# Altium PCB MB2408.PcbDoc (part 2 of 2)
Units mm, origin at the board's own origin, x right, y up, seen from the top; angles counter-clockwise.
Board outline 43 x 47 mm, 2 copper layers (Top Layer, Bottom Layer), stack 0.996 mm thick; 66 components, 54 nets, 306 pads, 690 vias.
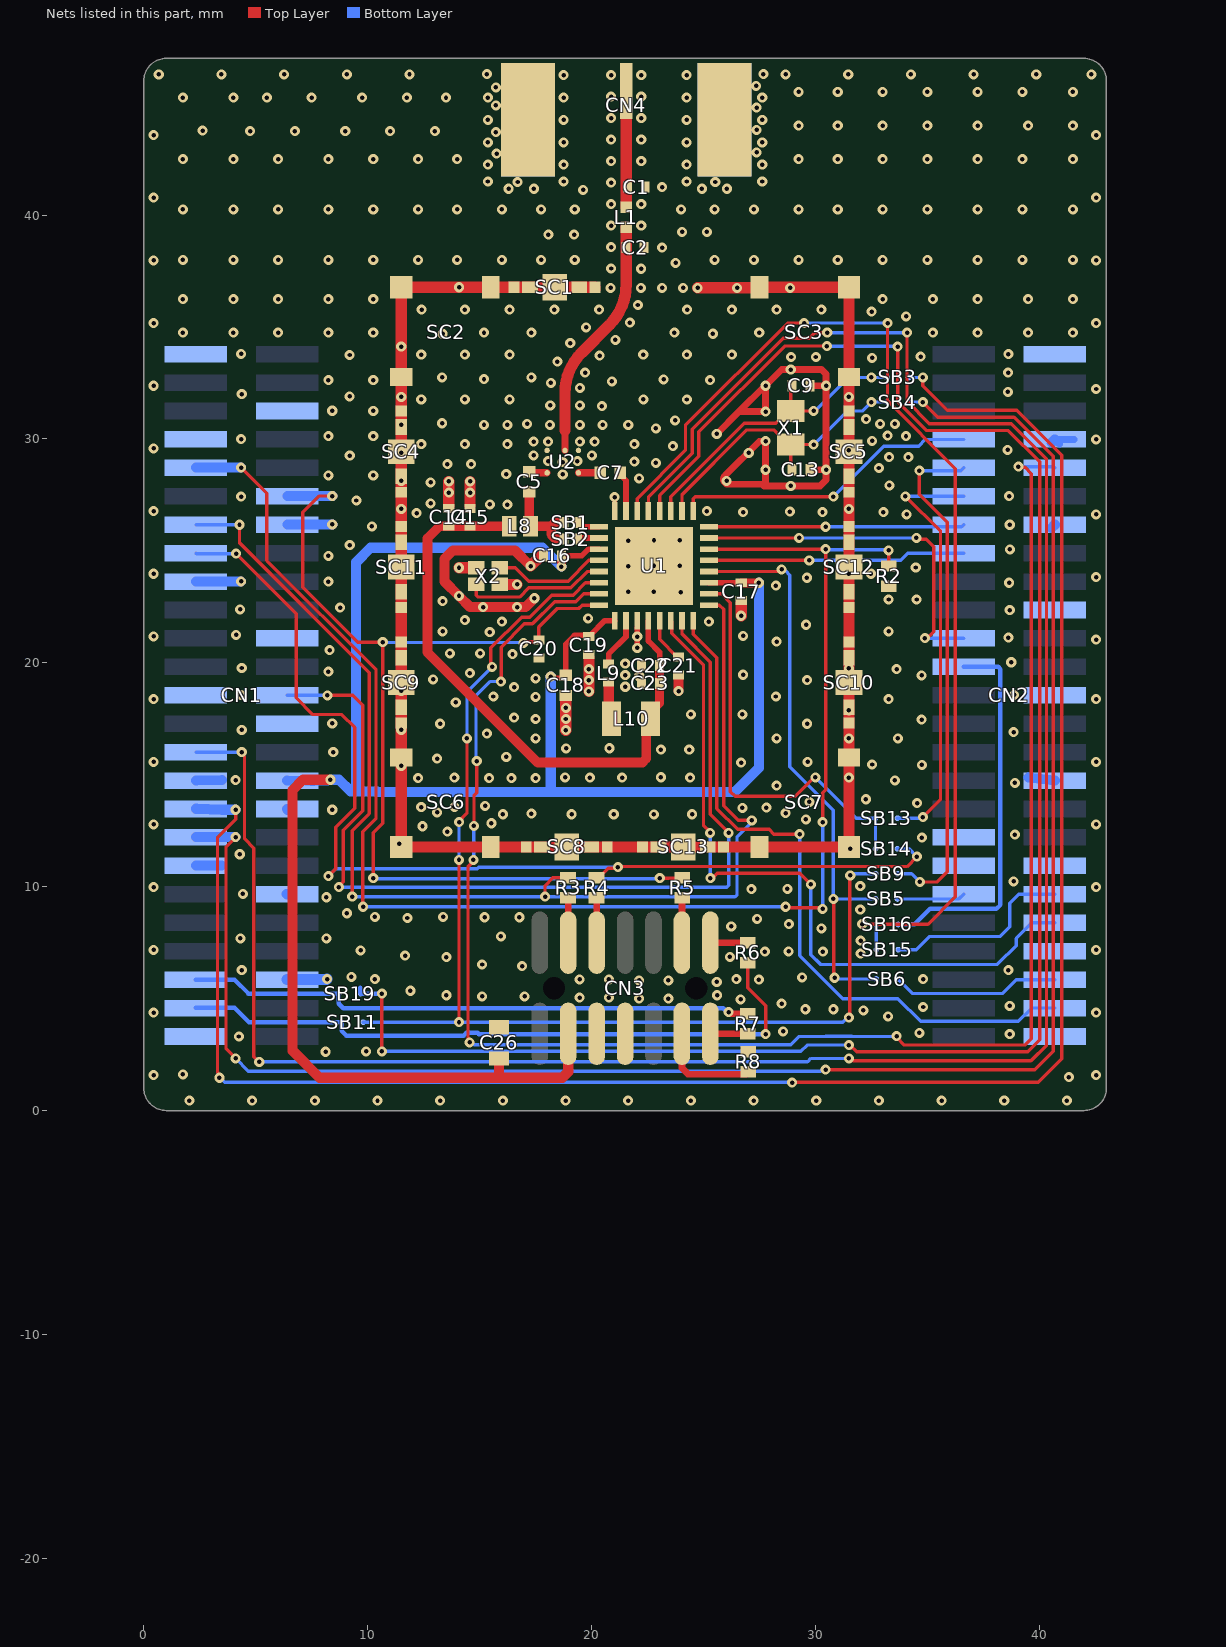
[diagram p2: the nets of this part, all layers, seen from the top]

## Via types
v1: diameter 0.45, hole 0.2, Top Layer to Bottom Layer, tented both sides, 690 vias

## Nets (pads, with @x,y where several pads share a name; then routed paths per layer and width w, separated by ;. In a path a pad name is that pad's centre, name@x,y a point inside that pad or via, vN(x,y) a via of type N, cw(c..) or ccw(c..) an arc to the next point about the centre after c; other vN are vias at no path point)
GND: C1.1 C2.1 C9.1 C13.1 C14.1 C15.1 C16.1 C17.1 C18.1 C19.2 C20.1 C21.1 C22.1 C23.1 C26.1 CN1.1 CN1.6 CN1.7 CN1.14 CN1.17 CN1.22 CN1.25 CN1.28 CN1.31 CN1.34 CN1.37 CN1.40 CN1.46 CN1.49 CN2.2 CN2.8 CN2.14 CN2.20 CN2.26 CN2.32 CN2.38 CN2.44 CN2.50 CN3.5 CN3.7 CN4.2 CN4.3 CN4.4 CN4.5 R2.1 R8.1 SC1.1 SC2.1 SC3.1 SC4.1 SC5.1 SC6.1 SC7.1 SC8.1 SC9.1 SC10.1 SC11.1 SC12.1 SC13.1 U1.16 U1.27 U1.33 U2.B1 U2.B3 X2.2 X2.4 | length 141
  Top Layer w0.2: v1(21.035,27.402) 21.038,27.399 21.038,26.78 U1.16@21.042,26.777
  Top Layer w0.25: v1(22.042,20.669) v1(22.042,21.17) U1.27@22.042,21.564
  Top Layer w0.3: v1@16.675,23.5 v1(16.68,23.505) ; SC1.1@20.16,36.775 20.16,36.765 SC1.1@20.25,36.675 ; v1(25.594,30.226) 26.593,31.225 ; C13.1@29.8,28.625 v1(30.475,28.625) ; C9.1@29.8,32.375 v1(30.475,32.375) ; 26.593,31.225 v1(27.775,31.225) v1(27.775,32.375) ; 26.593,31.225 27.743,32.375 v1(27.775,32.375) ; 27.775,27.975 27.7,27.9 v1(28.9,27.9) 30.214,27.9 30.475,28.161 v1(30.475,28.625) ; 27.775,27.975 v1(27.775,28.625) v1(27.775,29.9) 27.766,29.891 27.491,29.891 25.959,28.359 ccw(c26.118,28.2) 26.118,27.975 27.775,27.975 ; v1(27.775,32.375) 28.5,33.1 v1(28.9,33.1) 30.275,33.1 30.475,32.9 v1(30.475,32.375) ; v1(30.475,28.625) v1(30.475,32.375)
  Top Layer w0.45: v1(14.08,24.245) v1@14.085,24.25 ; v1(17.275,24.32) 16.57,25.025 13.809,25.025 13.425,24.642 13.425,23.642 v1(14.08,22.988) 14.58,22.488 v1(15.155,22.488) v1(16.68,22.488) 17.053,22.488 v1(17.449,22.883) ; v1@23.88,18.742 C21.1@23.88,19.339
  Top Layer w0.5: C14.1@13.625,27 v1(13.625,27.6) v1(13.625,28.1) ; v1@14.085,24.25 X2.4@14.855,24.25 ; C15.1@14.575,27 v1(14.575,27.6) v1(14.575,28.1) ; SC2.1@15.5,36.675 SC2.1@15.5,36.775 ; X2.2@15.905,23.5 v1@16.675,23.5 ; SC1.1@16.54,36.775 16.25,36.775 ; v1(17.275,24.32) 17.731,24.776 C16.1@17.759,24.776 ; v1(18.852,16.99) v1(18.852,17.49) v1(18.852,17.99) C18.1@18.852,18.39 ; v1(19.882,18.723) v1(19.882,19.223) v1(19.882,19.723) C19.2@19.882,20.223 ; SC1.1@20.16,36.775 SC1.1@19.45,36.775 SC1.1@18.35,36.775 SC1.1@17.25,36.775 SC1.1@16.54,36.775 16.267,36.775 ccw(c16.268,36.45) 16.25,36.775 ; v1(24.743,36.75) v1(26.5,36.75) SC3.1@27.475,36.75 ; v1(26.685,22.1) C17.1@26.685,22.675 ; SC3.1@27.5,36.775 SC3.1@31.5,36.775 SC3.1@31.5,32.775 SC5.1@31.5,31.243 SC5.1@31.5,30.533 SC5.1@31.5,29.433 SC5.1@31.5,28.333 SC5.1@31.5,27.623 31.5,26.875 SC12.1@31.5,26.088 SC12.1@31.5,25.378 31.5,25.078 31.5,24.578 SC12.1@31.5,24.278 v1(31.5,23.977) SC12.1@31.5,23.178 SC12.1@31.5,22.468 31.5,22.465 v1(31.5,19.75) v1(31.5,17.875) v1(31.5,16.625) SC7.1@31.5,15.775 v1(31.5,14.875) SC7.1@31.5,11.775 SC7.1@27.5,11.775 23.31,11.775 19.69,11.775 SC6.1@15.5,11.775 SC6.1@11.5,11.775 v1(11.5,15.395) SC6.1@11.5,15.775 SC9.1@11.5,17.31 SC9.1@11.5,18.02 SC9.1@11.5,19.12 SC9.1@11.5,20.22 SC9.1@11.5,20.93 SC11.1@11.5,22.468 SC11.1@11.5,23.178 SC11.1@11.5,24.278 SC11.1@11.5,25.378 SC11.1@11.5,26.088 SC4.1@11.5,27.623 SC4.1@11.5,28.333 v1(11.5,29.375) SC4.1@11.5,29.433 SC4.1@11.5,30.533 SC4.1@11.5,31.243 SC2.1@11.5,32.775 v1(11.5,34.125) SC2.1@11.5,36.775 SC2.1@15.5,36.775 ; SC2.1@15.5,36.775 16.25,36.775
  Bottom Layer w0.3: CN2.8@40.911,29.758 CN2.8@40.691,29.978 CN2.8@41.57,29.978
  Bottom Layer w0.45: CN1.37@2.343,10.94 CN1.37@3.462,10.943 ; CN1.31@2.343,14.75 CN1.31@3.501,14.762 ; CN1.17@2.343,23.64 v1(4.35,23.64) ; CN1.37@3.463,10.943 cw(c3.463,10.643) CN1.37@3.465,10.943 ; CN1.40@6.381,9.678 CN1.40@6.401,9.658 ; CN1.34@6.401,13.468 CN1.34@6.432,13.437 ; CN1.14@6.413,26.18 v1(8.42,26.18) ; CN2.32@39.521,14.883 CN2.32@40.691,14.738 ; CN2.14@40.546,26.023 CN2.14@40.691,26.168 ; CN2.8@40.546,29.833 CN2.8@40.691,29.978
  Bottom Layer w0.5: CN1.46@6.401,5.848 8.16,5.848 v1(8.187,5.875)
  other v1: 2.04,0.447 4.84,0.447 7.64,0.447 10.44,0.447 13.24,0.447 16.04,0.447 18.839,0.447 21.639,0.447 24.439,0.447 27.239,0.447 30.039,0.447 32.839,0.447 35.638,0.447 38.438,0.447 41.238,0.447 41.325,1.497 0.438,1.579 42.538,1.579 1.75,1.615 8.119,2.625 9.927,2.638 4.247,3.308 38.684,3.417 34.647,3.465 28.559,3.537 33.25,4.201 0.438,4.378 42.538,4.378 32.141,4.475 29.55,4.525 30.807,4.525 34.813,4.624 38.684,4.678 28.495,4.778 26.662,4.962 22.125,5 23.437,5 19.467,5.045 20.779,5.045 15.114,5.098 17.016,5.098 13.519,5.151 25.609,5.151 11.908,5.352 25.594,5.748 22.125,5.813 23.437,5.813 19.467,5.857 20.779,5.857 27.475,5.848 10.325,5.875 26.475,5.875 34.813,5.875 9.273,5.968 29.407,5.951 4.375,6.275 38.626,6.275 16.9,6.45 15.114,6.523 13.519,6.855 26.179,6.864 11.675,6.923 32.018,7.012 27.743,7.095 28.808,7.109 30.335,7.098 9.687,7.155 0.438,7.178 42.538,7.178 32.018,7.592 4.313,7.687 8.16,7.687 15.95,7.775 30.271,8.137 26.242,8.223 28.813,8.329 27.401,8.558 11.775,8.6 15.225,8.633 16.78,8.633 10.325,8.647 13.375,8.647 9.069,8.814 32.005,8.979 8.16,9.527 4.426,9.678 27.137,9.887 28.748,9.905 0.438,9.978 42.538,9.978 32.005,10.028 38.852,10.232 4.287,11.448 31.556,11.688 11.416,11.908 34.754,12.188 38.913,12.325 13.563,12.461 12.45,12.699 0.438,12.778 42.538,12.778 15.53,12.832 29.575,13.007 22.783,13.225 16.04,13.236 19.111,13.236 20.993,13.236 24.494,13.236 17.315,13.259 28.673,13.285 13.1,13.317 8.42,13.437 26.742,13.516 27.808,13.527 12.395,13.556 13.875,13.562 15.25,13.604 34.541,13.735 29.729,13.783 32.254,13.904 28.27,14.51 38.913,14.639 33.55,14.75 4.101,14.762 12.25,14.852 15.43,14.852 16.422,14.852 17.505,14.852 13.875,14.875 18.819,14.883 19.932,14.875 21.364,14.875 24.4,14.875 23.1,14.887 34.754,15.443 32.538,15.457 26.685,15.538 0.438,15.578 29.65,15.578 42.538,15.578 13.1,15.716 16.19,15.796 8.463,16.008 23.1,16.125 24.367,16.125 18.866,16.175 20.801,16.182 17.505,16.625 28.27,16.625 33.683,16.625 15.325,16.837 38.852,16.908 4.375,17 11.5,17 8.42,17.29 13.24,17.278 29.634,17.278 34.744,17.461 17.505,17.49 16.539,17.548 24.439,17.695 26.742,17.695 13.935,18.23 0.438,18.378 33.275,18.378 42.538,18.378 17.505,18.473 15.613,18.495 28.237,18.495 4.35,18.56 38.877,18.57 23.886,18.735 11.5,18.75 16.54,18.911 21.508,18.93 29.634,19.223 12.925,19.258 17.505,19.305 22.133,19.4 21.508,19.452 34.741,19.439 26.776,19.465 14.563,19.539 8.244,19.606 33.624,19.715 4.375,19.767 21.508,19.962 38.748,20.025 16.47,20.386 13.677,20.419 15.02,20.419 8.301,20.569 28.27,20.944 42.538,21.032 38.625,21.125 0.438,21.177 26.776,21.205 4.125,21.25 15.454,21.375 13.35,21.4 33.275,21.4 29.589,21.7 16,21.838 25.243,21.838 14.346,21.904 19.852,21.988 38.684,22.358 4.3,22.389 8.773,22.468 13.35,22.759 33.275,22.828 34.519,22.828 23.981,23.152 21.64,23.175 22.783,23.175 28.237,23.452 38.656,23.575 8.25,23.625 29.625,23.8 42.538,23.832 0.438,23.977 32.475,23.977 34.482,24.257 21.64,24.318 22.792,24.327 23.935,24.327 8.244,24.776 38.687,25.063 9.2,25.259 21.637,25.459 22.792,25.47 23.935,25.47 10.189,26.098 38.684,26.168 34.076,26.631 42.538,26.631 12.187,26.688 26.776,26.73 30.318,26.73 33.033,26.73 28.86,26.75 0.438,26.777 25.15,26.777 11.5,26.875 31.5,26.875 15.463,27.073 16.243,27.063 12.812,27.125 9.5,27.25 4.35,27.426 38.656,27.45 33.306,27.925 12.812,28.062 11.5,28.125 26.037,28.125 22.125,28.239 8.25,28.375 10.25,28.375 18.715,28.414 16.19,28.429 32.838,28.701 13.563,28.875 14.625,28.875 22.875,28.932 18.715,28.963 21.917,28.986 18.064,29.013 19.365,29.013 33.297,29.188 34.157,29.189 9.2,29.251 17.414,29.263 20.015,29.263 27.025,29.375 31.5,29.5 38.583,29.513 0.438,29.577 23.633,29.675 12.395,29.769 14.341,29.768 16.243,29.769 21.917,29.769 17.412,29.881 18.062,29.881 19.485,29.881 20.135,29.881 32.538,29.913 4.35,29.99 42.538,29.978 8.25,30.125 10.25,30.125 33.222,30.146 34.048,30.125 22.875,30.475 11.5,30.625 15.197,30.625 16.243,30.625 18.137,30.625 19.484,30.624 20.492,30.624 21.642,30.625 17.125,30.675 32.892,30.675 33.55,30.675 13.323,30.7 23.734,30.825 32.263,30.883 8.42,31.26 10.25,31.25 20.46,31.462 18.156,31.5 19.484,31.5 12.395,31.763 14.341,31.768 16.341,31.768 22.314,31.763 24.26,31.761 11.5,31.875 31.5,31.875 9.196,31.9 4.375,32 38.597,32.105 42.538,32.231 19.485,32.279 0.438,32.377 18.186,32.5 20.909,32.572 8.25,32.625 10.25,32.625 25.296,32.625 23.224,32.658 15.197,32.673 13.323,32.747 17.315,32.747 19.714,32.959 38.613,32.959 18.477,33.457 32.538,33.625 28.918,33.66 30.026,33.66 34.702,33.675 20.36,33.722 9.196,33.75 12.395,33.769 14.341,33.768 16.341,33.768 22.312,33.771 24.258,33.769 26.273,33.768 4.35,33.8 38.625,33.788 19.049,34.277 21.067,34.429 13.35,34.7 25.425,34.7 1.75,34.75 4,34.75 6,34.75 8.25,34.75 10.25,34.75 15.197,34.75 17.315,34.75 23.7,34.75 27.491,34.75 35.25,34.75 37.25,34.75 39.5,34.75 41.5,34.75 19.756,34.984 0.438,35.177 42.538,35.177 21.713,35.193 34.056,35.475 32.513,35.691 12.408,35.776 14.339,35.776 16.339,35.776 18.339,35.776 20.339,35.776 24.271,35.776 26.271,35.776 28.271,35.776 30.271,35.776 22.074,35.984 1.75,36.25 4,36.25 6,36.25 8.25,36.25 10.25,36.25 33,36.25 35.25,36.25 37.25,36.25 39.5,36.25 41.5,36.25 20.857,36.75 22.21,36.75 23.155,36.75 24.096,36.75 28.875,36.75 14.085,36.775 20.879,37.613 22.215,37.602 23.757,37.866 0.438,37.976 42.538,37.976 1.75,38 4,38 6,38 8.25,38 10.25,38 12.25,38 14,38 16,38 17.75,38 19.25,38 25.5,38 27.25,38 29.25,38 31,38 33,38 35,38 37.25,38 39.25,38 41.5,38 23.155,38.55 20.879,38.573 18.073,39.125 19.224,39.125 24.05,39.25 25.15,39.25 20.879,39.533 22.221,39.533 1.75,40.25 4,40.25 6,40.25 8.25,40.25 10.25,40.25 12.25,40.25 14,40.25 16,40.25 17.75,40.25 19.25,40.25 24,40.25 25.5,40.25 27.25,40.25 29.25,40.25 31,40.25 33,40.25 35,40.25 37.25,40.25 39.25,40.25 41.5,40.25 20.879,40.492 22.221,40.492 0.438,40.776 42.538,40.776 19.625,41.125 16.301,41.177 17.426,41.177 24.926,41.177 26.051,41.177 23.155,41.25 20.879,41.452 16.701,41.477 25.526,41.477 15.375,41.5 18.75,41.5 24.25,41.5 27.625,41.5 15.375,42.25 18.75,42.25 24.25,42.25 27.625,42.25 20.879,42.411 22.221,42.411 1.75,42.5 4,42.5 6,42.5 8.25,42.5 10.25,42.5 12.25,42.5 14,42.5 29.25,42.5 31,42.5 33,42.5 35,42.5 37.25,42.5 39.25,42.5 41.5,42.5 15.761,42.75 27.376,42.802 15.375,43.25 18.75,43.25 24.25,43.25 27.625,43.25 20.879,43.371 22.221,43.371 0.438,43.576 42.538,43.576 15.726,43.702 4.75,43.75 6.75,43.75 9,43.75 11,43.75 13,43.75 2.632,43.775 27.376,43.802 29.25,44 31,44 33,44 35,44 37.25,44 39.507,44 41.5,44 15.375,44.25 18.75,44.25 24.25,44.25 27.625,44.25 20.879,44.331 22.221,44.331 27.376,44.802 15.726,44.902 1.75,45.25 4,45.25 5.5,45.25 7.5,45.25 9.75,45.25 11.75,45.25 13.5,45.25 15.375,45.25 18.75,45.25 24.25,45.25 27.625,45.25 20.879,45.29 22.221,45.29 29.25,45.5 31,45.5 33,45.5 35,45.5 37.25,45.5 39.25,45.5 41.5,45.5 15.726,45.702 27.354,45.775 18.75,46.25 20.879,46.25 22.221,46.25 24.25,46.25 0.67,46.288 3.47,46.288 6.27,46.288 9.069,46.288 11.869,46.288 15.325,46.3 27.675,46.3 28.668,46.288 31.468,46.288 34.268,46.288 37.068,46.288 39.868,46.288 42.328,46.288
GPIO3/BOOT0: CN1.9 R2.2 U1.6 | length 69.8
  Top Layer w0.15: v1(4.35,28.72) 5.49,27.58 5.49,24.569 10.375,19.684 10.375,13.061 9.775,12.461 9.775,9.127 v1(9.8,9.102) ; U1.6@25.242,25.077 v1(30.457,25.077) 30.457,14.323 30.325,14.192 v1(30.325,12.886) ; v1(28.673,9.102) 28.72,9.055 30.278,9.055 v1(30.325,9.008) ; R2.2@33.275,24.325 v1(33.275,25.019)
  Bottom Layer w0.15: v1(9.8,9.102) v1(28.673,9.102) ; v1(30.325,9.008) v1(30.325,12.886) ; v1@30.457,25.063 30.471,25.048 33.246,25.048 v1(33.275,25.019)
  Bottom Layer w0.45: CN1.9@2.343,28.72 v1(4.35,28.72)
GPIO5/SWDIO: CN1.13 R3.2 U1.1 | length 54.8
  Top Layer w0.15: v1(4.275,26.168) 4.275,25.36 10.075,19.56 10.075,13.267 9.313,12.505 v1(9.313,9.555) ; v1(17.925,9.555) 17.925,10.049 18.276,10.4 R3.2@18.95,10.4 ; U1.1@25.242,22.577 25.712,22.577 25.9,22.389 25.9,13.615 26.554,12.961 v1(27.158,12.961)
  Bottom Layer w0.15: CN1.13@2.331,26.168 v1(4.275,26.168) ; v1(9.313,9.555) 26.412,9.555 26.5,9.643 26.5,12.222 27.158,12.88 v1(27.158,12.961)
GPIO6/SWCLK: CN1.15 R4.2 SB14.1 | length 48.4
  Top Layer w0.15: v1(4.126,24.875) 6.805,22.196 6.805,18.431 7.546,17.69 8.846,17.69 9.425,17.111 9.425,13.509 8.575,12.659 8.575,10.8 v1(8.25,10.475) ; R4.2@20.225,10.4 20.32,10.4 20.738,10.818 21.118,10.818 21.2,10.9 34.094,10.9 v1(34.532,11.338)
  Bottom Layer w0.15: CN1.15@2.331,24.898 2.354,24.875 v1(4.126,24.875) ; v1(8.25,10.475) 8.575,10.8 14.891,10.8 14.966,10.875 v1(21.175,10.875) ; SB14.1@33.662,11.688 34.182,11.688 v1(34.532,11.338)
GPIO12: CN1.26 U1.31 | length 42.2
  Top Layer w0.15: v1(8.2,18.548) 9.33,18.548 9.775,18.103 9.775,13.392 8.908,12.524 8.908,10.216 8.712,10.021 v1(8.712,9.978) ; U1.31@24.042,21.877 24.042,21.292 25.3,20.033 25.3,13.225 v1(26.125,12.4)
  Bottom Layer w0.15: CN1.26@6.401,18.548 v1(8.2,18.548) ; v1(8.712,9.978) 26.037,9.978 26.125,10.066 v1(26.125,12.4)
GPIO14: CN1.29 U1.13 | length 104.2
  Top Layer w0.15: v1(4.375,16.008) 4.375,15.927 4.501,15.801 4.501,12.137 4.916,11.722 4.916,2.405 5.143,2.177 v1(5.158,2.177) ; U1.13@22.542,26.777 22.545,26.78 22.545,27.402 24.497,29.355 24.497,30.438 28.559,34.5 29.725,34.5 29.975,34.75 v1(30.531,34.75) ; v1(31.5,2.325) 31.581,2.325 31.684,2.222 39.632,2.222 40.325,2.915 40.325,29.1 38.75,30.675 35.093,30.675 34.094,31.674 v1(34.094,34.75)
  Bottom Layer w0.15: CN1.29@2.331,16.008 v1(4.375,16.008) ; v1(5.158,2.177) 5.164,2.171 29.65,2.171 29.804,2.325 v1(31.5,2.325) ; v1(30.531,34.75) v1(34.094,34.75)
GPIO15/OSC32_IN: CN1.33 SB3.2 | length 87.8
  Top Layer w0.15: v1(3.375,1.465) 3.318,1.522 3.318,1.68 3.295,1.703 3.295,12.201 4.101,13.007 v1(4.101,13.437) ; v1(28.96,1.245) 28.983,1.268 39.958,1.268 41,2.31 41,29.274 38.999,31.275 35.891,31.275 34.8,32.366 v1(34.8,32.747)
  Bottom Layer w0.15: v1(3.375,1.465) 3.416,1.465 3.613,1.268 28.938,1.268 v1(28.96,1.245) ; SB3.2@34.1,32.747 SB3.2@34.175,32.747 v1(34.8,32.747)
  Bottom Layer w0.45: CN1.33@2.343,13.48 3.501,13.437 v1(4.101,13.437)
GPIO16/OSC32_OUT: CN1.35 SB4.2 | length 83.2
  Top Layer w0.15: v1(4.101,2.325) 3.675,2.751 3.675,11.784 v1(4.101,12.21) ; v1(30.457,1.828) 39.798,1.828 40.625,2.655 40.625,29.224 38.874,30.975 35.472,30.975 v1(34.8,31.647)
  Bottom Layer w0.15: v1(4.101,2.325) 4.669,1.757 30.219,1.757 30.232,1.77 30.399,1.77 v1(30.457,1.828) ; SB4.2@34.1,31.647 SB4.2@34.175,31.647 v1(34.8,31.647)
  Bottom Layer w0.45: CN1.35@2.343,12.21 v1(4.101,12.21)
GPIO23/VCP1_RX: CN1.45 R7.1 SB19.2 | length 25.5
  Top Layer w0.3: v1(26.125,4.4) 26.166,4.4 26.241,4.325 R7.1@26.975,4.325
  Bottom Layer w0.2: CN1.45@2.331,5.848 4.052,5.848 4.675,5.225 SB19.2@8.712,5.225 8.712,4.77 8.908,4.575 25.883,4.575 26.058,4.4 v1(26.125,4.4)
GPIO24/VCP1_TX: CN1.47 R6.2 SB11.1 | length 29.8
  Top Layer w0.15: R6.2@26.975,6.6 26.975,5.478 27.775,4.678 v1(27.775,3.417)
  Bottom Layer w0.2: CN1.47@2.331,4.598 4.052,4.598 4.7,3.95 SB11.1@8.825,3.95 8.835,3.94 8.835,3.565 9.05,3.35 14.284,3.35 14.399,3.465 14.909,3.465 14.958,3.417 v1(27.775,3.417)
GPIO28: CN2.7 U1.9 | length 13.7
  Top Layer w0.15: U1.9@24.542,26.777 24.542,27.328 24.634,27.42 v1(30.8,27.42)
  Bottom Layer w0.15: v1(30.8,27.42) 33.055,29.675 34.614,29.675 34.917,29.978 CN2.7@36.621,29.978
GPIO29: CN2.9 SB9.1 | length 23
  Top Layer w0.15: v1(34.647,28.585) 34.647,27.525 35.891,26.281 35.891,10.66 35.441,10.21 v1(34.667,10.21)
  Bottom Layer w0.15: SB9.1@33.662,10.582 34.297,10.582 v1(34.667,10.21) v1(34.667,10.21) ; v1(34.647,28.585) 36.498,28.585 CN2.9@36.621,28.708
GPIO30: CN2.10 U1.23 | length 77.2
  Top Layer w0.15: v1(14.557,3.042) 14.5,3.099 14.5,3.262 14.483,3.279 14.483,10.887 14.725,11.13 v1(14.725,11.2) ; v1(14.75,12.711) 14.75,14.071 14.875,14.196 v1(14.875,15.613) ; v1(15.95,19.164) 15.96,19.174 15.96,20.699 16.999,21.738 17.363,21.738 18.351,22.725 19.303,22.725 19.654,23.077 U1.23@20.342,23.077 ; v1(33.624,3.328) 33.624,3.264 33.963,2.925 39.35,2.925 39.637,3.212 39.637,28.455 39.365,28.728 39.1,28.728 v1(39.064,28.763)
  Bottom Layer w0.15: v1(14.557,3.042) 14.614,2.984 14.712,2.984 14.758,2.938 28.903,2.938 29.273,3.308 30.438,3.308 30.455,3.325 31.621,3.325 31.638,3.308 33.604,3.308 v1(33.624,3.328) ; v1(14.725,11.2) 14.737,11.212 14.737,12.699 v1(14.75,12.711) ; v1(14.875,15.613) 14.837,15.651 14.837,18.538 15.463,19.164 v1(15.95,19.164) ; v1(39.064,28.763) 40.636,28.763 CN2.10@40.691,28.708
GPIO31: CN2.11 SB13.1 | length 19.1
  Top Layer w0.15: v1(34.025,27.438) 35.591,25.872 35.591,13.898 v1(34.8,13.107)
  Bottom Layer w0.15: SB13.1@33.662,13.061 34.754,13.061 v1(34.8,13.107) ; v1(34.025,27.438) CN2.11@36.621,27.438
GPIO33: CN2.13 U1.8 | length 11.4
  Top Layer w0.15: U1.8@25.242,26.077 v1(30.457,26.077)
  Bottom Layer w0.15: v1(30.457,26.077) 32.947,26.077 32.949,26.075 36.528,26.075 CN2.13@36.621,26.168
GPIO34: CN2.15 U1.5 | length 11.5
  Top Layer w0.15: U1.5@25.242,24.577 25.243,24.576 29.724,24.576 v1(29.725,24.575)
  Bottom Layer w0.15: v1(29.725,24.575) 33.808,24.575 34.131,24.898 CN2.15@36.621,24.898
GPIO37: CN2.21 U1.7 | length 16.3
  Top Layer w0.15: U1.7@25.242,25.577 v1(29.273,25.577) ; v1(34.512,25.577) 34.57,25.52 34.962,25.52 35.291,25.19 35.291,21.387 35.114,21.21 35.079,21.21 34.969,21.1 v1(34.887,21.1)
  Bottom Layer w0.15: v1(29.273,25.577) v1(34.512,25.577) ; v1(34.887,21.1) 36.609,21.1 CN2.21@36.621,21.088
GPIO39: CN2.23 SB16.1 | length 17.2
  Bottom Layer w0.2: SB16.1@33.7,8.313 34.444,8.313 34.444,8.329 35.122,9.008 38.09,9.008 38.266,9.184 38.266,19.715 38.163,19.818 CN2.23@36.621,19.818
GPIO47: CN2.35
GPIO49: CN2.37
GPIO50: CN2.39 SB5.1 | length 3
  Bottom Layer w0.15: SB5.1@33.662,9.452 36.415,9.452 CN2.39@36.621,9.658
GPIO51: CN2.40 SB15.1 | length 8.6
  Bottom Layer w0.15: SB15.1@33.7,7.187 34.512,7.187 35.1,7.775 38.259,7.775 38.684,8.2 38.684,9.263 39.08,9.658 CN2.40@40.691,9.658
GPIO53: CN2.42 U1.30 | length 32.2
  Top Layer w0.15: U1.30@23.542,21.877 23.592,21.827 23.592,21.318 24.388,20.522 25,19.909 25,12.74 25.296,12.444 v1(25.296,12.4) ; v1(25.306,10.378) 25.387,10.378 25.609,10.6 29.303,10.6 v1(29.801,10.102)
  Bottom Layer w0.15: v1(25.296,12.4) 25.301,12.395 25.301,10.383 v1(25.306,10.378) ; v1(29.801,10.102) 29.801,6.962 30.24,6.523 38.109,6.523 38.163,6.577 38.179,6.577 38.965,7.362 38.965,7.687 39.666,8.388 CN2.42@40.691,8.388
GPIO56: CN2.46 SB6.1 | length 7.5
  Bottom Layer w0.15: SB6.1@33.696,5.875 34.346,5.225 38.342,5.225 38.965,5.848 CN2.46@40.691,5.848
GPIO57: CN2.48 U1.32 | length 31.3
  Top Layer w0.15: U1.32@24.542,21.877 24.542,21.281 25.6,20.223 25.6,13.491 26.53,12.561 27.932,12.561 28.143,12.35 v1(29.299,12.35)
  Bottom Layer w0.15: v1(29.299,12.35) 29.299,6.923 31.222,5 33.683,5 34.7,3.983 39.071,3.983 39.666,4.578 CN2.48@40.691,4.578
NetC1_2: C1.2 CN4.1 L1.2 | length 5.2
  Top Layer w0.51: L1.2@21.55,40.35 21.55,41.25 CN4.1@21.55,45.55
NetC2_2: C2.2 L1.1 U2.B2 | length 10.9
  Top Layer w0.32: U2.B2@18.815,29.488 18.815,30.378
  Top Layer w0.51: 18.816,30.378 18.816,32.058 cw(c21.356,32.058) 19.56,33.854 20.806,35.1 ccw(c19.01,36.896) 21.55,36.896 C2.2@21.55,38.55 L1.1@21.55,39.45
NetC5_1: C5.1 U2.A1 | length 0.8
  Top Layer w0.32: C5.1@17.225,28.488 U2.A1@18.016,28.488
NetC5_2: C5.2 L8.2 SB1.2 SB2.2 | length 4.2
  Top Layer w0.43: L8.2@17.215,26.11 C5.2@17.215,27.673 ; L8.2@17.225,26.221 ccw(c17.396,26.221) L8.2@17.275,26.1 18.193,26.1 ; SB1.2@18.698,26.266 18.359,26.266 18.193,26.1 ; SB2.2@18.76,25.535 18.399,25.535 18.193,25.74 18.193,26.1
NetC7_1: C7.1 U1.15 | length 1.8
  Top Layer w0.25: C7.1@21.24,28.488 21.24,28.438 21.542,28.137 U1.15@21.542,26.777
NetC7_2: C7.2 U2.A3 | length 1
  Top Layer w0.32: U2.A3@19.415,28.488 C7.2@20.44,28.488
NetC9_2: C9.2 SB3.1 U1.11 X1.2 | length 13.8
  Top Layer w0.15: U1.11@23.542,26.777 23.542,27.426 26.815,30.7 28.237,30.7 28.35,30.813 28.35,30.825 28.775,31.25 X1.2@28.9,31.25 ; C9.2@28.9,32.375 X1.2@28.9,31.25 ; v1@30.075,31.25 X1.2@28.9,31.25
  Bottom Layer w0.15: v1(29.925,31.25) 30,31.25 31.497,32.747 v1(32.5,32.747) SB3.1@33.2,32.747
NetC13_2: C13.2 SB4.1 U1.10 X1.1 | length 13.3
  Top Layer w0.15: U1.10@24.042,26.777 24.042,27.502 26.939,30.4 28.149,30.4 28.35,30.199 28.35,30.175 28.775,29.75 X1.1@28.9,29.75 ; C13.2@28.9,28.625 X1.1@28.9,29.75 ; v1(29.925,29.75) X1.1@28.9,29.75
  Bottom Layer w0.15: v1(29.925,29.75) 31.422,31.247 32.1,31.247 v1(32.5,31.647) SB4.1@33.2,31.647
NetC21_2: C21.2 U1.29 | length 2
  Top Layer w0.15: U1.29@23.042,21.877 23.042,21.049 23.833,20.258 C21.2@23.883,20.258
NetCN3_4: CN3.4 R3.1 | length 2
  Top Layer w0.3: R3.1@18.95,9.5 18.96,9.49 CN3.4@18.96,7.5
NetCN3_6: CN3.6 R4.1 | length 2
  Top Layer w0.3: R4.1@20.225,9.5 20.23,9.495 CN3.6@20.23,7.5
NetCN3_11: CN3.11 R8.2 | length 4.7
  Top Layer w0.3: CN3.11@24.04,3.43 24.04,1.897 24.312,1.625 26.903,1.625 R8.2@27.003,1.725 ; R8.2@26.914,1.814 R8.2@26.928,1.828
NetCN3_12: CN3.12 R5.1 | length 2
  Top Layer w0.3: CN3.12@24.04,7.5 24.04,9.49 R5.1@24.05,9.5
NetCN3_13: CN3.13 R7.2 | length 1.7
  Top Layer w0.3: CN3.13@25.31,3.43 25.315,3.425 R7.2@26.975,3.425
NetCN3_14: CN3.14 R6.1 | length 1.7
  Top Layer w0.3: CN3.14@25.31,7.5 R6.1@26.975,7.5
NetL9_1: L9.1 L10.2 | length 1.1
  Top Layer w0.47: L10.2@20.765,17.935 L9.1@20.765,18.993
NetL9_2: L9.2 U1.26 | length 2.3
  Top Layer w0.25: L9.2@20.765,19.921 20.765,20.386 21.542,21.163 U1.26@21.542,21.877
NetSB1_1: SB1.1 U1.17 | length 1
  Top Layer w0.25: SB1.1@19.375,26.266 ccw(c19.832,26.723) 19.832,26.077 U1.17@20.342,26.077
NetSB2_1: SB2.1 U1.18 | length 1
  Top Layer w0.25: SB2.1@19.375,25.525 19.427,25.577 U1.18@20.342,25.577
NetSB5_2: SB5.2 SB6.2 U1.4 | length 26.4
  Top Layer w0.15: U1.4@25.242,24.077 28.315,24.077 28.414,24.176 v1(28.495,24.176) ; v1(30.8,9.452) 30.828,9.424 30.828,5.959 v1(30.856,5.931)
  Bottom Layer w0.15: v1(28.495,24.176) 28.577,24.176 28.648,24.105 28.668,24.105 28.86,23.913 28.86,15.352 30.8,13.412 v1(30.8,9.452) SB5.2@32.687,9.452 ; v1(30.856,5.931) 30.913,5.875 SB6.2@32.721,5.875
NetSB9_2: SB9.2 SB11.2 U1.22 | length 52.7
  Top Layer w0.15: v1(14.08,3.95) v1(14.08,11.2) ; v1(14.085,12.886) 14.085,12.933 14.437,13.285 v1(14.437,16.625) ; v1(15.56,19.818) 15.504,19.874 15.504,20.667 16.875,22.038 17.239,22.038 18.227,23.025 19.178,23.025 19.73,23.577 U1.22@20.342,23.577 ; v1(31.498,4.147) 31.527,4.176 31.527,10.471 v1(31.556,10.5)
  Bottom Layer w0.15: SB11.2@9.8,3.95 31.22,3.95 31.417,4.147 v1(31.498,4.147) ; v1(14.08,11.2) 14.083,11.202 14.083,12.884 v1(14.085,12.886) ; v1(14.437,16.625) 14.437,18.695 v1(15.56,19.818) ; v1(31.556,10.5) 31.638,10.5 31.72,10.582 SB9.2@32.687,10.582
NetSB13_2: SB13.2 SB14.2 U1.2 | length 18.6
  Top Layer w0.15: U1.2@25.242,23.077 25.808,23.077 26.2,22.685 26.2,14.246 26.411,14.035 29.102,14.035 29.95,14.883 v1(30,14.883)
  Bottom Layer w0.15: v1(30,14.883) 31.822,13.061 SB13.2@32.687,13.061 SB14.2@32.687,11.688
NetSB15_2: SB15.2 SB16.2 U1.14 | length 49
  Top Layer w0.15: U1.14@22.042,26.777 22.042,27.33 24.197,29.486 24.197,30.606 28.77,35.178 v1(29.5,35.178) ; v1(32.093,8.329) 35.034,8.329 36.25,9.545 36.25,28.669 33.222,31.697 v1(33.222,35.178)
  Bottom Layer w0.15: v1(29.5,35.178) v1(33.222,35.178) ; v1(32.093,8.329) 32.109,8.313 SB16.2@32.725,8.313 SB15.2@32.725,7.187
NetSB19_1: SB19.1 U1.12 | length 84.1
  Top Layer w0.15: v1(10.632,2.64) v1(10.632,5.226) ; U1.12@23.042,26.777 23.042,27.475 24.797,29.23 24.797,30.314 28.633,34.15 v1(30.518,34.15) ; v1(31.5,2.925) 31.544,2.925 31.844,2.625 39.496,2.625 40.025,3.154 40.025,26.088 40.015,26.098 40.015,28.986 38.626,30.375 34.969,30.375 33.675,31.669 v1(33.675,34.125)
  Bottom Layer w0.15: v1(10.632,2.64) 29.349,2.64 29.634,2.925 v1(31.5,2.925) ; v1(30.518,34.15) 30.531,34.137 33.663,34.137 v1(33.675,34.125)
  Bottom Layer w0.2: 9.677,5.487 9.677,5.271 SB19.1@9.687,5.26 ; SB19.1@9.687,5.225 v1(10.632,5.226)
NetU1_20: U1.20 X2.3 | length 5.1
  Top Layer w0.15: X2.3@15.905,24.25 16.597,24.25 17.197,23.65 18.955,23.65 19.882,24.577 U1.20@20.342,24.577
NetU1_21: U1.21 X2.1 | length 6.5
  Top Layer w0.15: X2.1@14.855,23.5 14.855,23.025 14.943,22.938 16.784,22.938 17.197,23.35 19.079,23.35 19.806,24.077 U1.21@20.342,24.077
NRST: C20.2 CN1.12 R5.2 U1.24 | length 46.8
  Top Layer w0.15: v1(8.42,27.45) 7.825,27.45 7.105,26.73 7.105,23.379 9.561,20.922 v1(10.675,20.922) 10.675,12.834 10.25,12.409 v1(10.25,10.378) ; v1(16.958,20.887) 17.016,20.945 17.576,20.945 C20.2@17.65,21.019 17.65,21.6 18.476,22.425 19.427,22.425 19.579,22.577 U1.24@20.342,22.577 ; v1(23.048,10.378) 24.028,10.378 R5.2@24.05,10.4
  Bottom Layer w0.15: v1(10.25,10.378) 10.281,10.347 23.017,10.347 v1(23.048,10.378) ; v1(10.675,20.922) 10.692,20.905 16.941,20.905 v1(16.958,20.887)
  Bottom Layer w0.45: CN1.12@6.413,27.45 v1(8.42,27.45)
VDD: C16.2 C17.2 C18.2 C19.1 C26.2 CN1.32 CN3.3 U1.3 U1.19 U1.25 | length 94.3
  Top Layer w0.2: v1(18.18,19.379) 18.192,19.285 cw(c18.316,19.161) 18.316,19.336 18.695,19.336 18.853,19.339 C18.2@18.875,19.339 ; C18.2@18.875,19.34 18.875,20.296
  Top Layer w0.25: C16.2@18.65,24.776 19.557,24.776 19.858,25.077 U1.19@20.342,25.077 ; C18.2@18.853,19.339 18.853,20.836 19.239,21.223 19.932,21.223 20.586,21.877 U1.25@21.042,21.877 ; U1.3@25.242,23.577 26.683,23.577 C17.2@26.685,23.575
  Top Layer w0.4: C16.2@18.65,24.776 18.65,24.303 v1(18.653,24.301) ; C17.2@26.685,23.575 v1(27.475,23.575)
  Top Layer w0.45: v1(8.338,14.778) 7.105,14.778 6.65,14.323 6.65,2.666 7.851,1.465 9.025,1.465 15.875,1.465 ; C26.2@15.875,2.325 15.875,1.465 ; CN3.3@18.96,3.43 18.96,1.733 18.692,1.465 15.875,1.465
  Bottom Layer w0.45: CN1.32@6.401,14.738 7.503,14.712 ccw(c7.509,15.012) CN1.32@7.63,14.738 ; CN1.32@7.63,14.75 8.179,14.75 ccw(c8.179,15.05) v1@8.244,14.757 ; v1(8.338,14.778) 8.718,14.778 9.239,14.257 10.434,14.257 10.463,14.229 26.401,14.229 27.475,15.304 v1(27.475,23.575) ; 9.487,14.461 9.487,24.496 10.132,25.14 17.814,25.14 v1(18.653,24.301) ; 18.18,14.257 v1(18.18,19.379)
VFBSD: C14.2 C15.2 C22.2 C23.2 L8.1 L10.1 U1.28 | length 27.3
  Top Layer w0.25: U1.28@22.542,21.877 22.542,20.973 23.048,20.467 C22.2@23.048,20.025
  Top Layer w0.4: L10.1@22.446,17.505 22.446,17.606 23.033,18.193 C23.2@23.033,19.077 23.033,19.127 C22.2@23.033,19.873
  Top Layer w0.43: L8.1@16.272,26.1 C15.2@14.575,26.1 C14.2@13.625,26.1 13.21,26.1 12.674,25.564 12.674,20.467 17.595,15.546 22.276,15.546 22.446,15.716 L10.1@22.446,17.505
pads on no net: CART-1.1 CN1.2 CN1.3 CN1.4 CN1.5 CN1.8 CN1.10 CN1.11 CN1.16 CN1.18 CN1.19 CN1.20 CN1.21 CN1.23 CN1.24 CN1.27 CN1.30 CN1.36 CN1.38 CN1.39 CN1.41 CN1.42 CN1.43 CN1.44 CN1.48 CN1.50 CN2.1 CN2.3 CN2.4 CN2.5 CN2.6 CN2.12 CN2.16 CN2.17 CN2.18 CN2.19 CN2.22 CN2.24 CN2.25 CN2.27 CN2.28 CN2.29 CN2.30 CN2.31 CN2.33 CN2.34 CN2.36 CN2.41 CN2.43 CN2.45 CN2.47 CN2.49 CN3.1 CN3.2 CN3.8 CN3.9 CN3.10 CN3.NPTH1 CN3.NPTH2

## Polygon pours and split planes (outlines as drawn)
GND on Bottom Layer "GAGND_L02_P003" (solid, remove dead copper, pour order 3): 0,47 43,47 43,0 0,0
GND on Top Layer "GND_L01_P001" (solid, remove dead copper, pour order 1): 0,47 43,47 43,0 0,0

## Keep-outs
Top Layer:
  region: 14.155,23.87 14.08,23.87 cw(c14.08,24.25) 13.7,24.25 cw(c14.075,24.25) 14.075,24.625 15.225,24.625 15.225,23.875
  region: 13.091,26.75 13.091,28.091 cw(c13.625,28.091) 13.625,28.625 cw(c13.625,28.1) 14.15,28.1 14.15,26.75 14,26.75
  region: 14.041,26.75 14.041,28.091 cw(c14.575,28.091) 14.575,28.625 cw(c14.575,28.1) 15.1,28.1 15.1,26.75 14.95,26.75
  region: 15.954,24.804 19.448,24.804 19.448,25.74 15.954,25.74
Keep-Out Layer:
  lines w0.1: 41.875,-0.025 1.086,-0.025 cw(c1.086,1.088) -0.026,1.085 -0.026,45.891 cw(c1.086,45.888) 1.086,47.001 41.919,47 ; 41.917,47.001 cw(c41.916,45.889) 43.029,45.891 ; 41.919,-0.025 ccw(c41.916,1.088) 43.029,1.087 43.029,46

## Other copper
Top Layer:
  region net GND: 24.85,22.225 24.85,21.325 25.6,20.575 25.63,20.605 25.63,22.228
  region net GND: 18.142,28.76 18.165,28.748 18.187,28.734 18.208,28.718 18.227,28.701 18.245,28.681 18.261,28.66 18.275,28.638 18.287,28.615 18.297,28.591 18.305,28.566 18.31,28.54 18.314,28.515 18.315,28.488 18.315,28.163 19.115,28.163 19.115,28.488 19.116,28.515 19.12,28.54 19.125,28.566 19.133,28.591 19.143,28.615 19.155,28.638 19.169,28.66 19.185,28.681 19.203,28.701 19.222,28.718 19.243,28.734 19.265,28.748 19.288,28.76 19.312,28.77 19.337,28.778 19.363,28.784 19.389,28.787 19.415,28.788 19.74,28.788 19.74,28.988 20.49,28.988 20.49,30.113 19.114,30.113 19.114,29.488 19.113,29.462 19.11,29.436 19.104,29.411 19.096,29.386 19.086,29.362 19.074,29.338 19.06,29.316 19.044,29.296 19.026,29.276 19.007,29.259 18.986,29.243 18.964,29.229 18.941,29.217 18.917,29.206 18.892,29.199 18.866,29.193 18.84,29.19 18.814,29.188 18.788,29.19 18.762,29.193 18.736,29.199 18.711,29.206 18.687,29.217 18.664,29.229 18.642,29.243 18.621,29.259 18.602,29.276 18.584,29.296 18.568,29.316 18.554,29.338 18.542,29.362 18.532,29.386 18.524,29.411 18.519,29.436 18.515,29.462 18.514,29.488 18.514,30.113 16.94,30.113 16.94,28.988 17.69,28.988 17.69,28.788 18.015,28.788 18.041,28.787 18.067,28.784 18.093,28.778 18.118,28.77
  region net GND: 22.434,20.215 21.29,20.215 21.29,18.615 22.433,18.615
  region net GND: 27.775,30.094 27.775,28.044 25.893,28.044 25.777,28.161
  region net GND: 27.775,32.541 27.775,31.085 26.269,31.085
  region net NetC2_2: 18.591,30.275 18.656,30.142 18.818,30.142 18.819,30.141 18.976,30.141 19.039,30.275
  pour cut-out: 16.63,26.371 15.094,26.371 15.094,26.759 16.63,26.759
  pour cut-out: 21.672,30.378 21.672,27.277 16.488,27.277 16.488,30.378 18.098,30.378 19.536,30.378
  pour cut-out: 26.296,22.329 27.189,22.329 27.189,21.569 26.296,21.569
  pour cut-out: 24.05,18.593 24.828,18.593 24.828,18.365 24.05,18.365
  pour cut-out: 19.514,18.956 19.514,16.434 24.096,16.434 24.096,18.924
  pour cut-out: 18.5,21.768 19.537,21.768 19.537,20.296 18.5,20.296
  pour cut-out: 18.359,20.296 19.509,20.296 19.509,16.434 18.359,16.434
  pour cut-out: 13.865,24.825 13.617,24.577 13.617,23.738 14.647,22.708 15.261,22.708 15.261,24.823
  pour cut-out: 28.5,32.938 28.588,33.025 30.193,33.025 30.309,32.909 30.309,28.089 30.313,28.085 30.29,28.062 28.128,28.062 27.924,28.266 27.924,32.362

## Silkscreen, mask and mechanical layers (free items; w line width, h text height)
Top Overlay:
  text "J" at 31.675,41.686 h10
  text "MB2408A" at 30.963,39.013 h2.3
  text "H" at 7.912,38.4 h10
  text "K" at 2.052,38.289 h8
  text "E" at 7.539,6.607 h9
  text "I" at 36.886,3.613 h10
M1-Board Shape:
  the board outline again, w0.1
M10-Bottom Stiffener:
  drawing of 4390 lines, arcs and shapes, not listed
  text "Generated with the LayoutEditor (This message will NOT added in any commercial version of the LayoutEditor.)" at 11.217,33.906 h0
Drill Drawing:
  drawing of 166 lines, arcs and shapes, not listed
  text "PCB SPECIFICATIONS :" at -22.541,97.137 h3
  text "TG-150" at 51.675,93.175 h3
  text "A.   MATERIAL :" at -22.541,93.137 h3
  text "FR-4" at 15.959,93.137 h3
  text "TG-170" at 32.459,93.137 h3
  text "X   TG-140" at 66.1,93.1 h3
  text "B.   MATERIAL FAMILY :" at -22.541,90.137 h3
  text "VT-47" at 15.959,90.137 h3
  text "C.   SOLDERMASK COLOR :" at -22.541,87.137 h3
  text "GREEN" at 15.959,87.137 h3
  text "X  BLUE" at 32.459,87.137 h3
  text "RED" at 50.709,87.137 h3
  text "BLACK" at 66.709,87.137 h3
  text "D.   SILKSCREEN COLOR :" at -22.541,84.137 h3
  text "X  WHITE" at 15.959,84.137 h3
  text "YELLOW" at 32.459,84.137 h3
  text "BLACK" at 50.709,84.137 h3
  text "E.   SURFACE FINISH :" at -22.541,81.137 h3
  text "X  ENIG" at 15.959,81.137 h3
  text "IMMERSION SILVER" at 32.459,81.137 h3
  text "IMMERSION TIN" at 66.709,81.137 h3
  text "HASL" at 15.959,78.137 h3
  text "HASL (PB-FREE)" at 32.459,78.137 h3
  text "GOLDEN FINGER" at 66.709,78.137 h3
  text "F.   IMPEDANCE CONTROL :" at -22.541,75.137 h3
  text "NO" at 15.959,75.137 h3
  text "X  YES" at 32.459,75.137 h3
  text "G.   THROUGH VIA :" at -22.541,72.137 h3
  text "PLUG THE VIAS WHICH ARE COVERED WITH SOLDERMASK ONE OR TWO SIDE." at 15.959,72.137 h3
  text "PLUG MATERIAL :" at 15.959,69.137 h3
  text "X  SOLDERMASK" at 41.459,69.137 h3
  text "NON-CONDUCTIVE EPOXY." at 66.709,69.137 h3
  text "H.   STACK-UP :" at -22.541,66.137 h3
  text "SEE LAYER STACK-UP SEQUENCE FOR OVERALL THICKNESS." at 15.959,66.137 h3
  text "PCB : TYPE 3" at 110.088,57.996 h3
  text "ASPECT-RATIO, AXE Z :" at 110.088,52.496 h3
  text "6 :1 à 8 :1 / LEVEL \"B\"" at 110.107,45.749 h3
  text "Layer" at 50.841,44.7 h1.8
  text "Name" at 58.372,44.7 h1.8
  text "Material" at 72.928,44.7 h1.8
  text "Thickness" at 86.013,44.7 h1.8
  text "Constant" at 96.758,44.7 h1.8
  text "Top Overlay" at 58.372,41.1 h1.8
  text "Top Solder" at 58.372,37.5 h1.8
  text "Solder Resist" at 72.928,37.5 h1.8
  text "0,010mm" at 86.013,37.5 h1.8
  text "3.5" at 96.758,37.5 h1.8
  text "1" at 50.841,33.9 h1.8
  text "Top Layer" at 58.372,33.9 h1.8
  text "Copper" at 72.928,33.9 h1.8
  text "0,041mm" at 86.013,33.9 h1.8
  text "MINIMUN PARAMETERS" at 109.5,32.02 h3
  text "Dielectric 2" at 58.372,30.3 h1.8
  text "FR4" at 72.928,30.3 h1.8
  text "0,914mm" at 86.013,30.3 h1.8
  text "4.3" at 96.758,30.3 h1.8
  text "2" at 50.84,26.7 h1.8
  text "Bottom Layer" at 58.372,26.7 h1.8
  text "Copper" at 72.928,26.7 h1.8
  text "0,041mm" at 86.013,26.7 h1.8
  text "DEFAULT" at 109.5,26.52 h3
  text "Bottom Solder" at 58.372,23.1 h1.8
  text "Solder Resist" at 72.928,23.1 h1.8
  text "0,010mm" at 86.013,23.1 h1.8
  text "3.5" at 96.758,23.1 h1.8
  text "TRACKS : 0.150mm           / GAPS : 0.150mm" at 109.5,20.77 h3
  text "Bottom Overlay" at 58.372,19.5 h1.8
  text "Symbol" at 51.124,12.706 h2.16
  text "Count" at 59.586,12.706 h2.16
  text "Hole Size" at 68.371,12.706 h2.16
  text "Plated" at 83.813,12.706 h2.16
  text "Hole Type" at 91.241,12.706 h2.16
  text "Drill Layer Pair" at 102.056,12.706 h2.16
  text "Via/Pad" at 122.554,12.706 h2.16
  text "Hole Length" at 131.416,12.706 h2.16
  text "690" at 59.586,8.978 h1.8
  text "0.20mm (7.87mil)" at 68.371,8.978 h1.8
  text "PTH" at 83.813,8.978 h1.8
  text "Round" at 91.241,8.978 h1.8
  text "Top Layer - Bottom Layer" at 102.056,8.978 h1.8
  text "Via" at 122.554,8.978 h1.8
  text "-" at 131.416,8.978 h1.8
  text "2" at 59.586,5.25 h1.8
  text "1.00mm (39.37mil)" at 68.371,5.25 h1.8
  text "NPTH" at 83.813,5.25 h1.8
  text "Round" at 91.241,5.25 h1.8
  text "Top Layer - Bottom Layer" at 102.056,5.25 h1.8
  text "Pad" at 122.554,5.25 h1.8
  text "-" at 131.416,5.25 h1.8
  text "692 Total" at 59.586,1.522 h1.8

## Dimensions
1,0 to 1,47 on M2-Board Dimensions
0,1 to 43,1 on M2-Board Dimensions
